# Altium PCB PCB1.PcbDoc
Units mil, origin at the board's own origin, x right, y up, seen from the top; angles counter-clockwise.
Board outline 2756 x 2756 mil, 4 copper layers (Top Layer, Internal Plane 1, Internal Plane 2, Bottom Layer), stack 18.2 mil thick; 13 components, 14 nets, 56 pads, 0 vias.
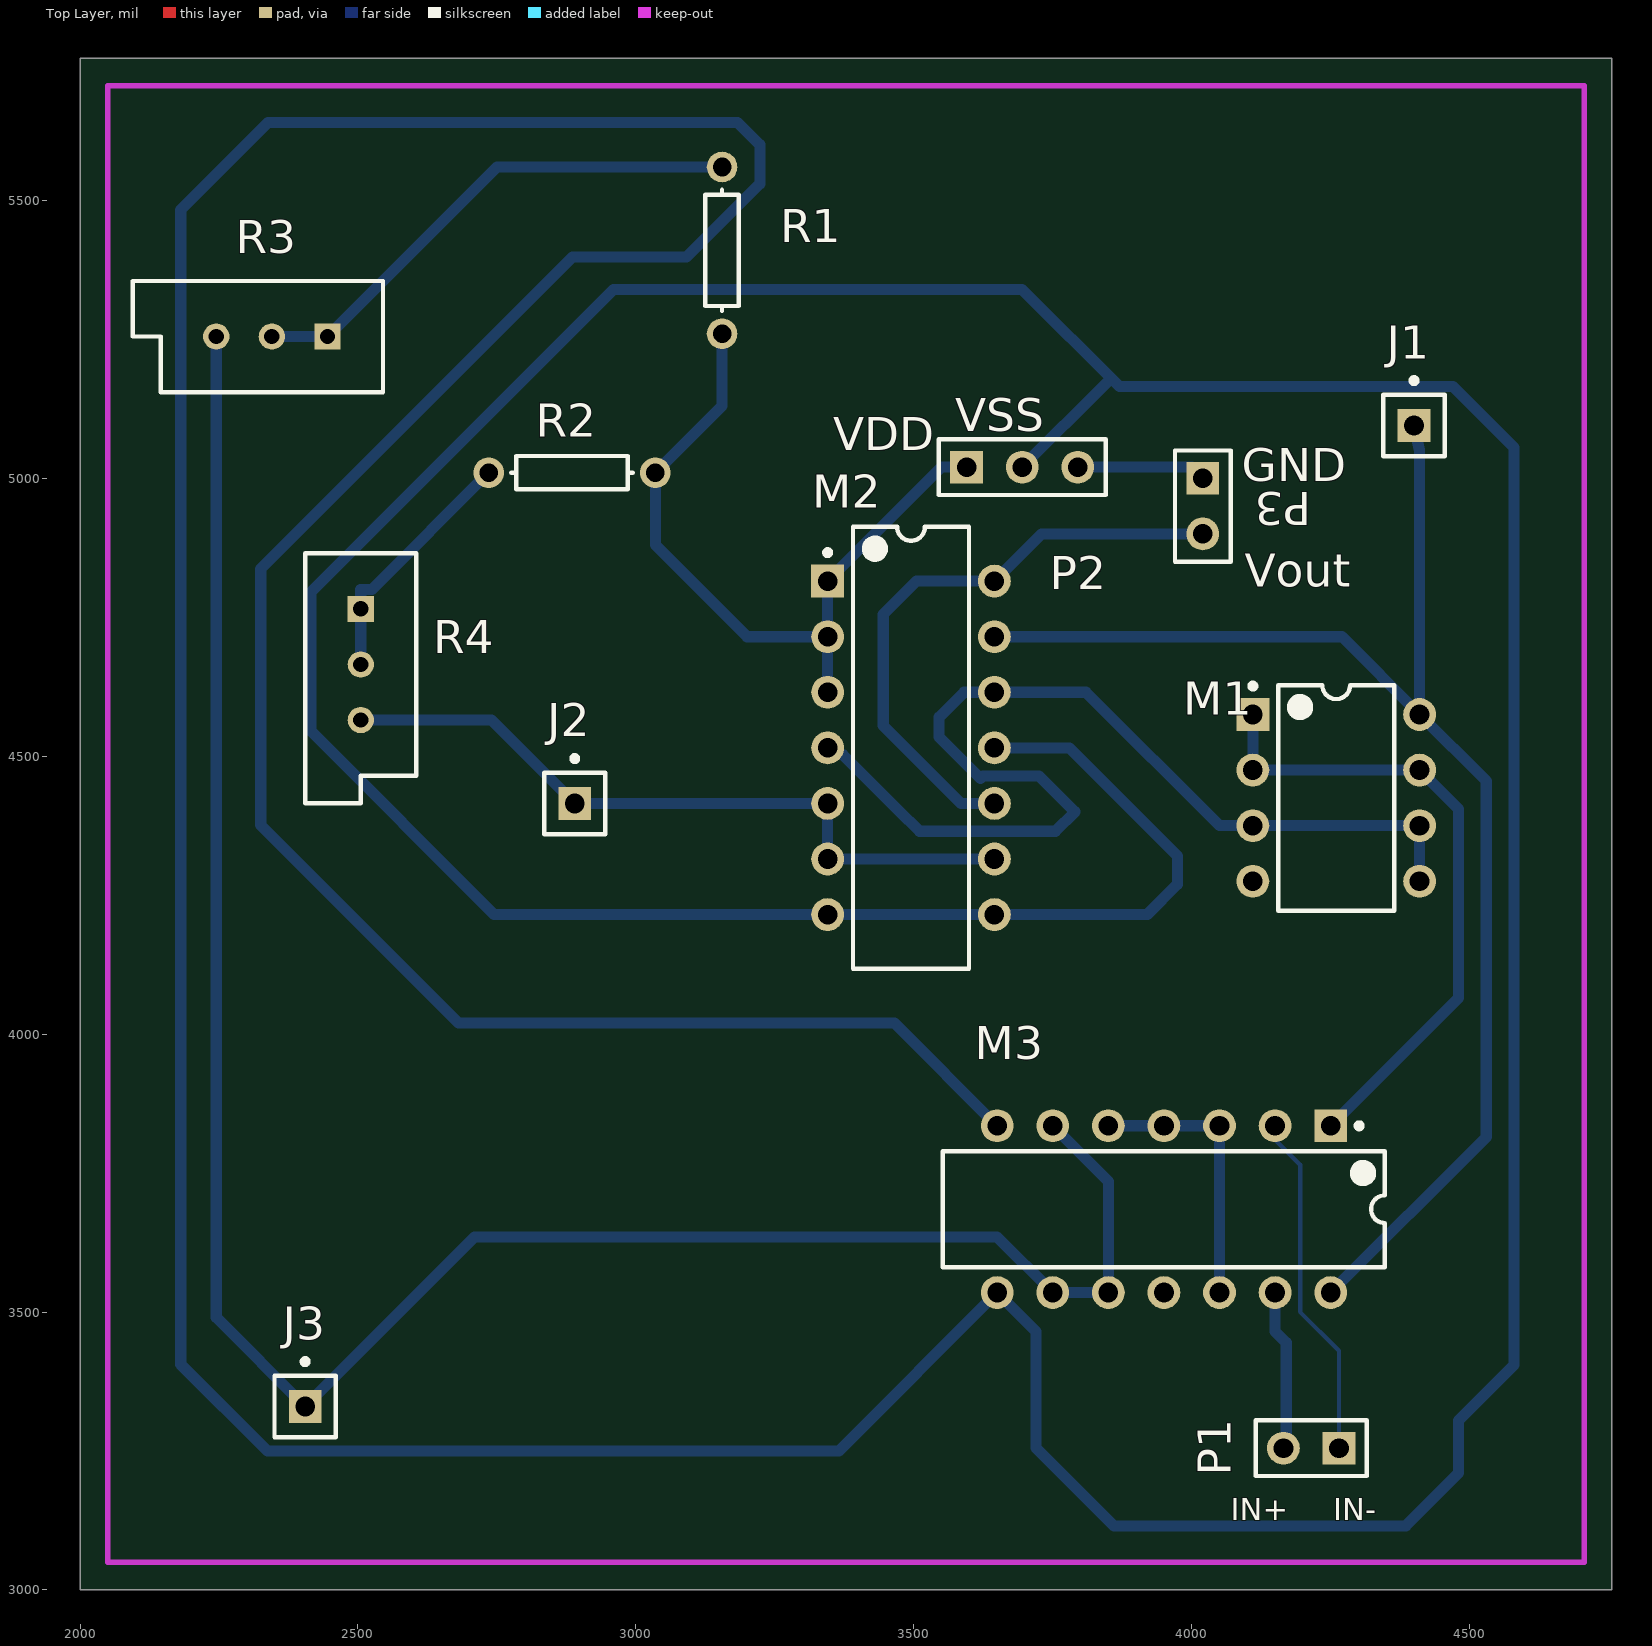
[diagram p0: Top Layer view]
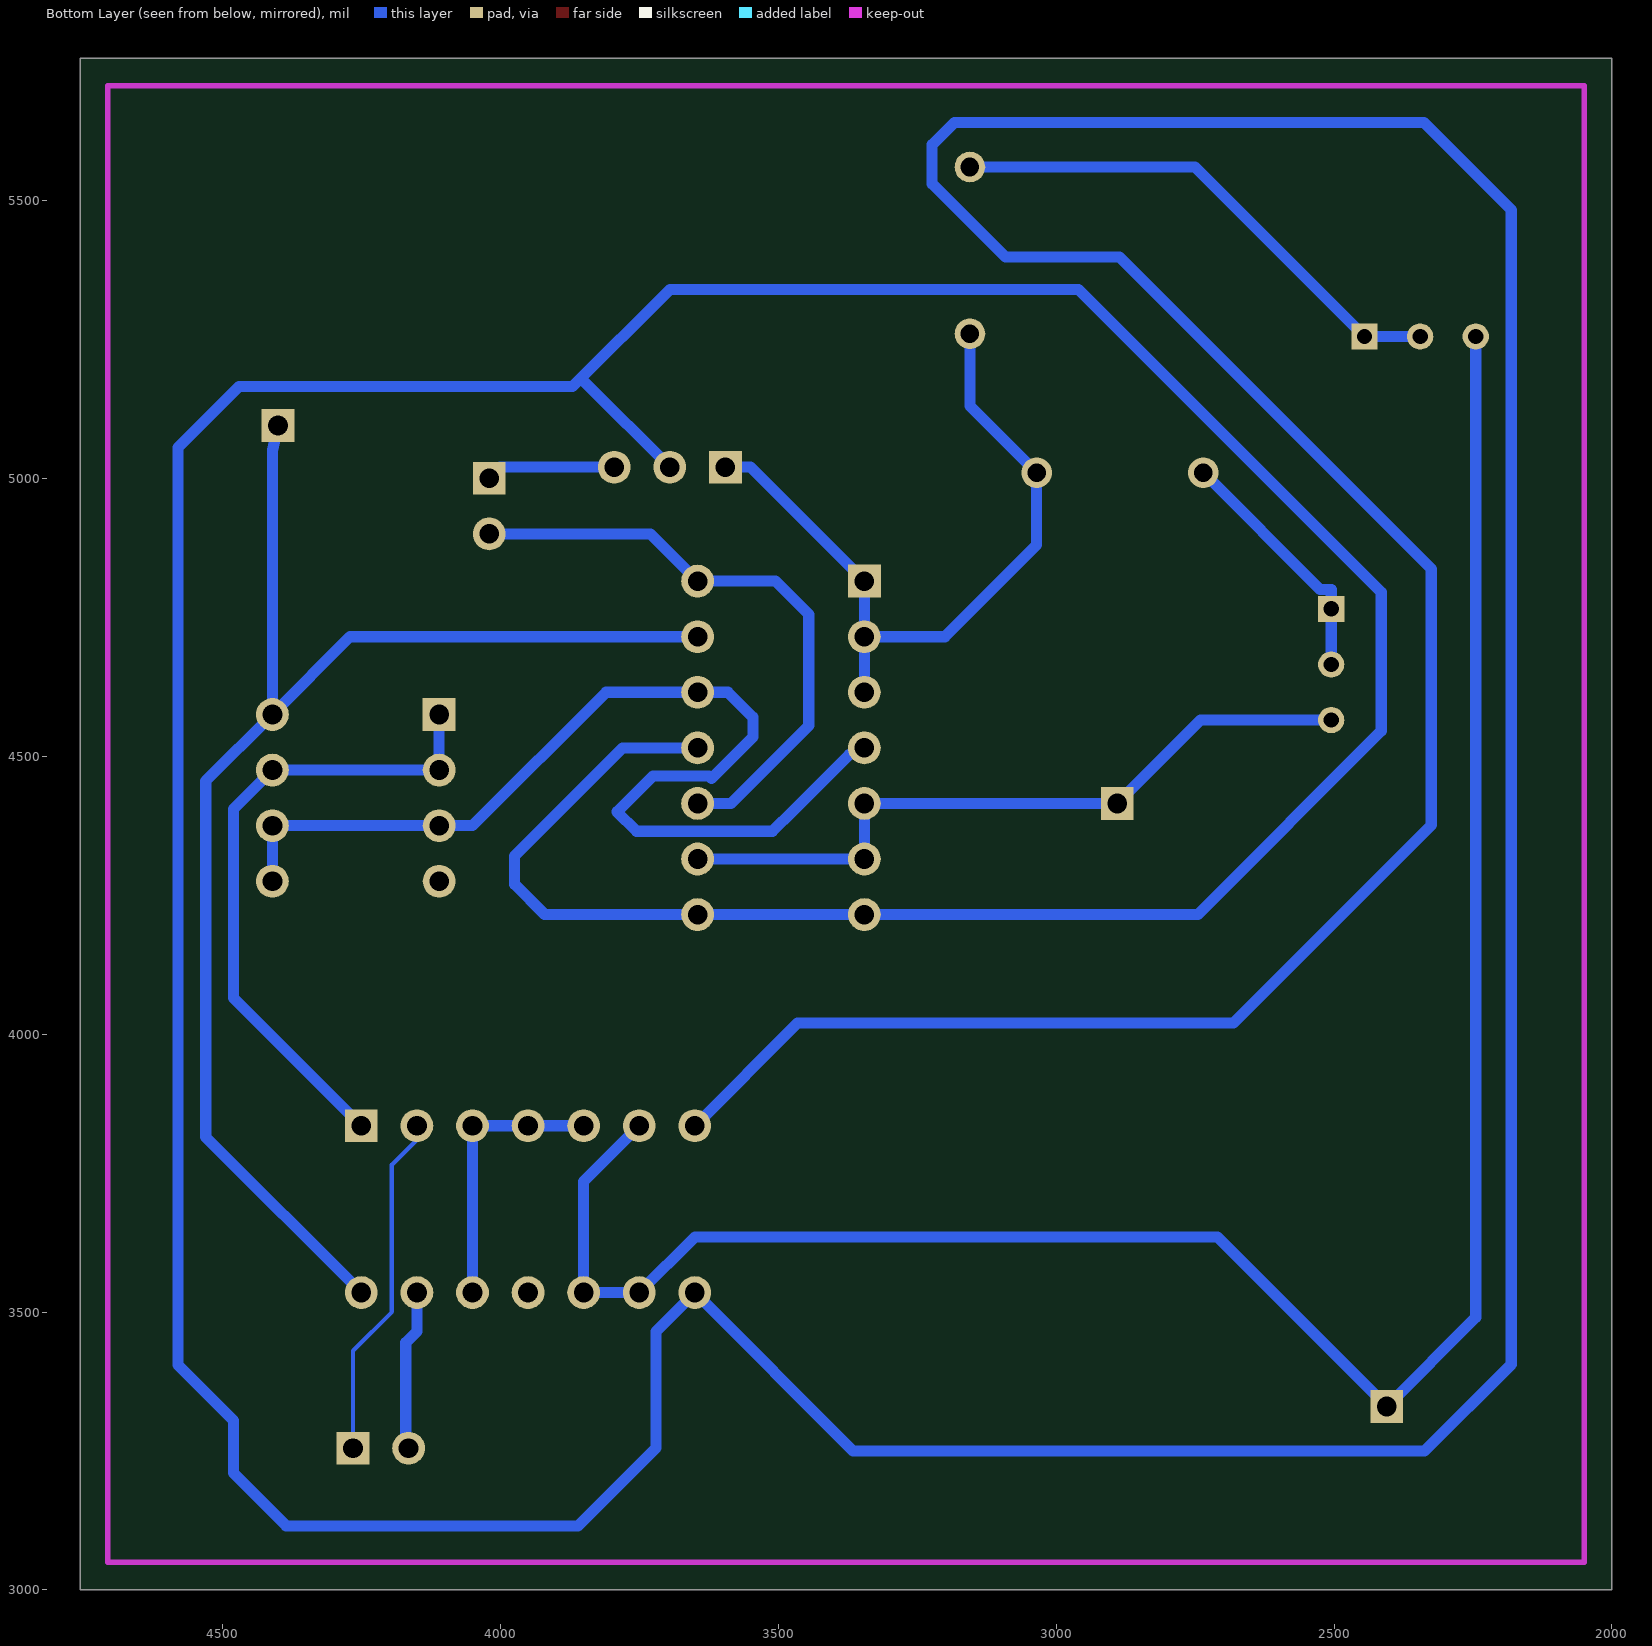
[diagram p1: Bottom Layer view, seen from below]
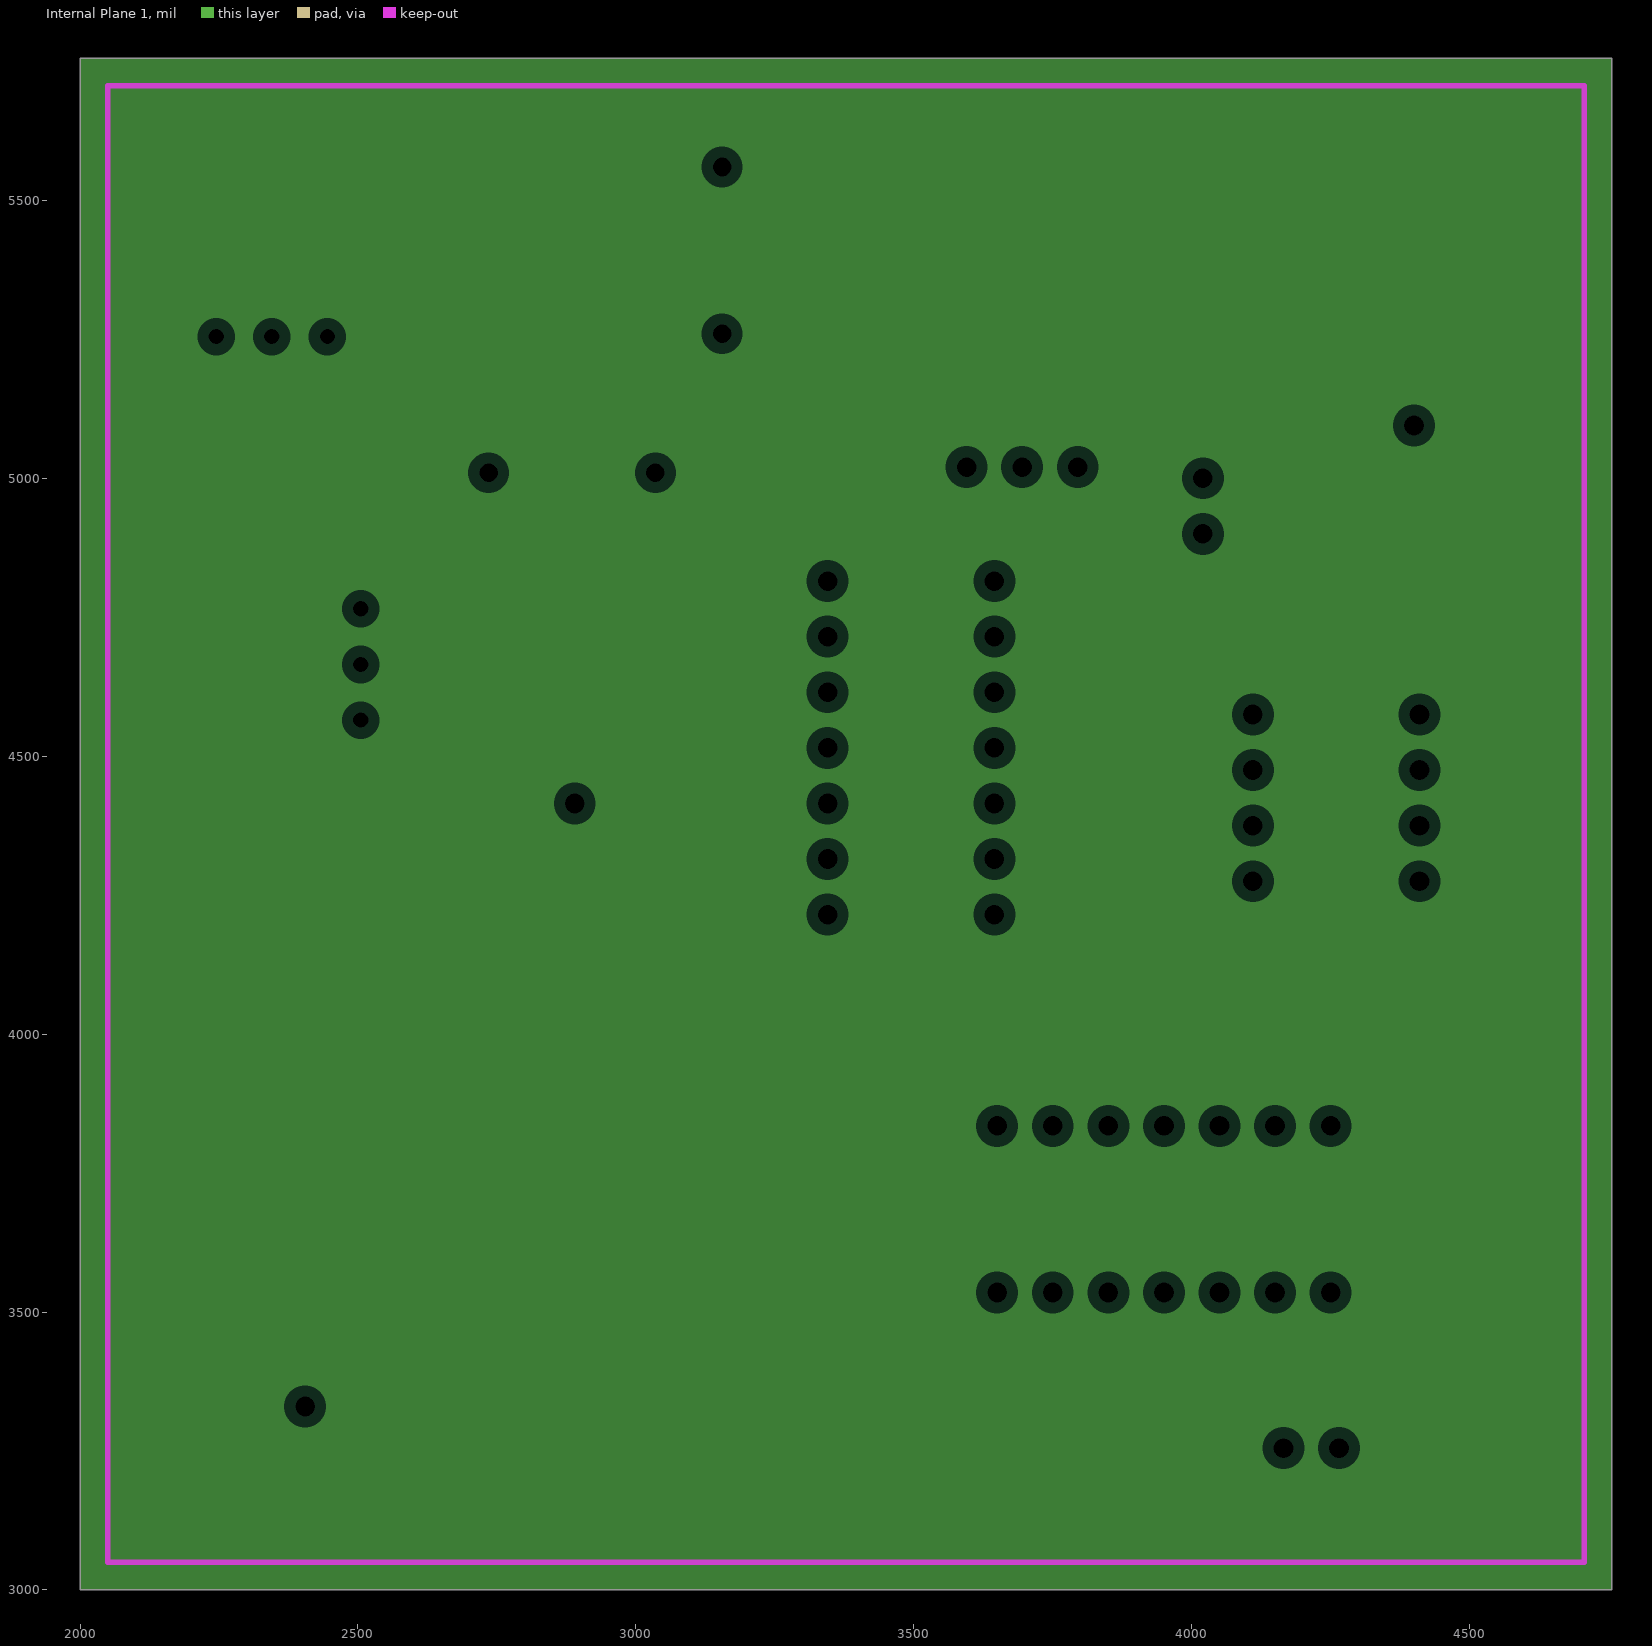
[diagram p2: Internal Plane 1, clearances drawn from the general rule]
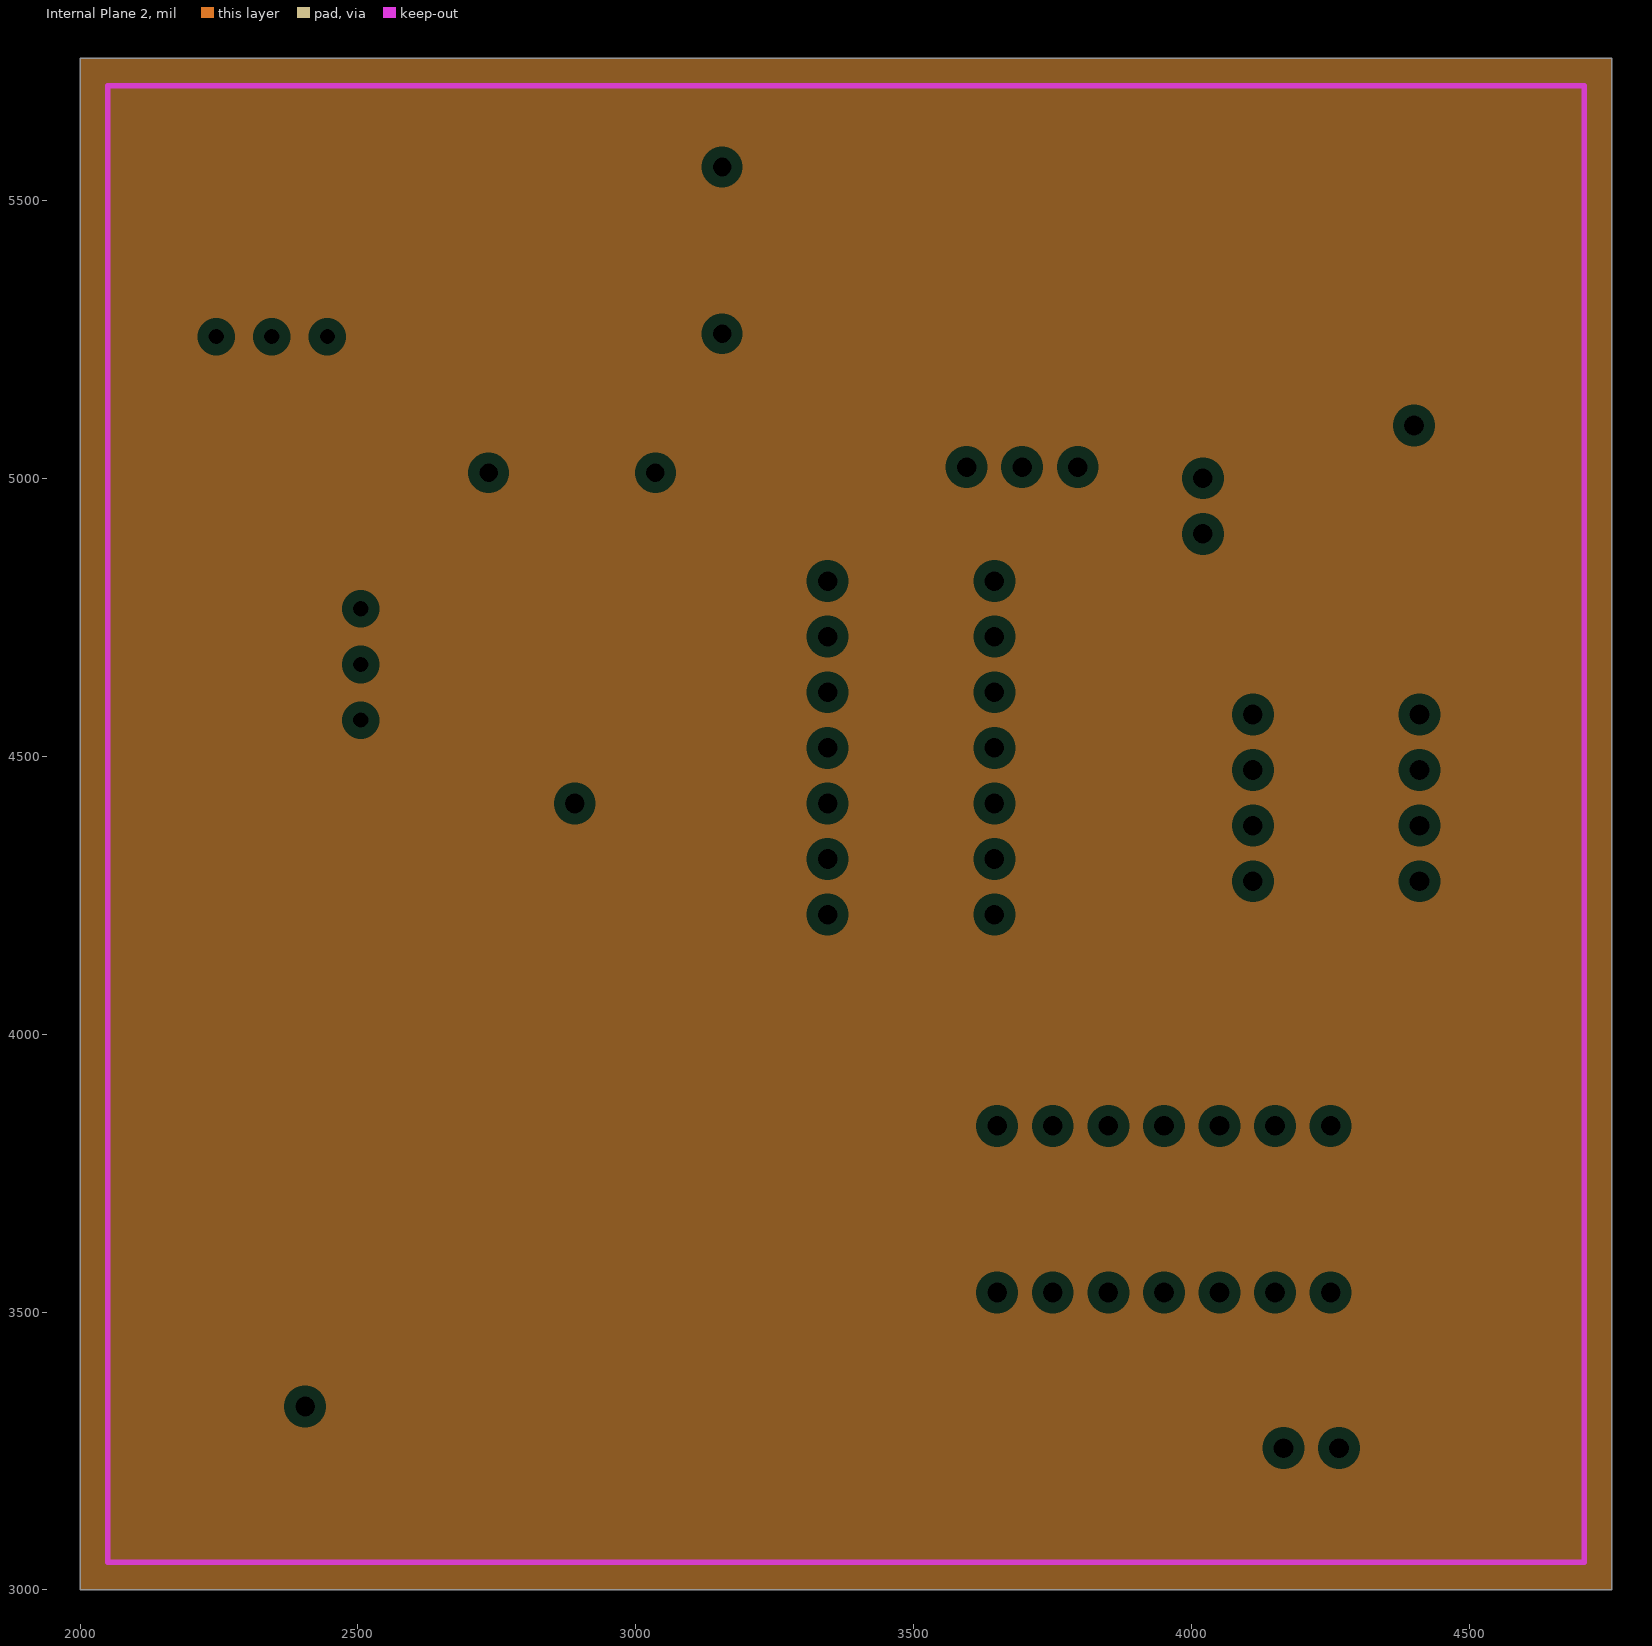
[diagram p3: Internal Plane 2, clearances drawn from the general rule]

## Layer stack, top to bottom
Top Solder: solder mask 0.4, Solder Resist, Dk 3.5
Top Layer: signal copper 1.4
Internal Plane 1: plane copper 1.4
Internal Plane 2: plane copper 1.4
Dielectric 1: dielectric 12.6, FR-4, Dk 4.8
Bottom Layer: signal copper 1.4
Bottom Solder: solder mask 0.4, Solder Resist, Dk 3.5

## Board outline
2000,3000 4756,3000 4756,5756 2000,5756

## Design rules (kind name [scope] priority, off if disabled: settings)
Clearance Clearance_3 [InNet('NetM1_3')] p1: gap=10
Clearance Clearance_2 [InNet('NetJ1_1')] p2: gap=10
Clearance Clearance_1 [InNet('IN+')] p3: gap=0
Clearance [All] p4: gap=30
PlaneClearance [All] p1: clearance=20
PlaneConnect [All] p1: planeconnectstyle=Relief reliefexpansion=20 reliefentries=4 reliefconductorwidth=10 reliefairgap=10
PolygonConnect [All] p1: connectstyle=Relief reliefconductorwidth=10 reliefentries=4 polygonreliefangle="90 Angle" airgapwidth=10
RoutingVias [All] p1: holewidth=32 width=62 viastyle="Through Hole" minholewidth=28 minwidth=50 maxholewidth=28 maxwidth=50
SolderMaskExpansion [All] p1: expansion=4
Width [All] p1: maxlimit=20 minlimit=8 preferedwidth=20 toplayer_minwidth=20 minimp=50.000000 maximp=50.000000 favimp=50.000000
28 further rules are at their usual default settings.

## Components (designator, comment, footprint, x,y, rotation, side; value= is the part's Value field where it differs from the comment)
J1 "Socket" PIN1 4400,5095 r0 top
J2 "Socket" PIN1 2890,4415 r0 top
J3 "Socket" PIN1 2405,3330 r0 top
M1 "ALD1117" DIP-8 4260,4425 r0 top
M2 "ALD1105" DIP-14 3495,4515 r0 top
M3 "ALD1106" DIP-14 3950,3685 r270 top
P1 "Header 2" HDR1X2 4265,3255 r180 top
P2 "Header 3" HDR1X3 3595,5020 r0 top
P3 "Header 2" HDR1X2 4020,5000 r270 top
R1 "Res1" AXIAL-0.3 3155,5410 r270 top
R2 "Res1" AXIAL-0.3 2885,5010 r0 top
R3 "RPot" VR5 2345,5255 r180 top
R4 "RPot" VR5 2505,4665 r270 top

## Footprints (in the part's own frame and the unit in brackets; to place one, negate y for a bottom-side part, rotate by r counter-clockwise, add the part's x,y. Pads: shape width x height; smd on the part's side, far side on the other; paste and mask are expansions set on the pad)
AXIAL-0.3 [mm] "Axial Device, Thru-Hole; 2 Leads; 0.3 in Pin Spacing"
  round 1.4 hole 0.85: 1(-3.81,0) 2(3.81,0)
  silkscreen extent -2.77,-0.76 2.77,0.76
DIP-8 [mm] "DIP, 8-Pin, Row Spacing 7.62 mm, Pitch 2.54 mm"
  rect 1.5x1.5 hole 0.9: 1(-3.81,3.81)
  round 1.5 hole 0.9: 2(-3.81,1.27) 3(-3.81,-1.27) 4(-3.81,-3.81) 5(3.81,-3.81) 6(3.81,-1.27) 7(3.81,1.27) 8(3.81,3.81)
  silkscreen extent -3.93,-5.15 2.65,5.23, body extent -3.6,-5.15 3.6,5.15, height 5.33
DIP-14 [mm] "DIP, 14-Pin, Row Spacing 7.62 mm, Pitch 2.54 mm"
  rect 1.5x1.5 hole 0.9: 1(-3.81,7.62)
  round 1.5 hole 0.9: 2(-3.81,5.08) 3(-3.81,2.54) 4(-3.81,0) 5(-3.81,-2.54) 6(-3.81,-5.08) 7(-3.81,-7.62) 8(3.81,-7.62) 9(3.81,-5.08) 10(3.81,-2.54) 11(3.81,0) 12(3.81,2.54) 13(3.81,5.08) 14(3.81,7.62)
  silkscreen extent -3.93,-10.1 2.65,10.1, body extent -3.6,-10.1 3.6,10.1, height 5.08
HDR1X2 [mm] "Connector; Header; 2 Position"
  rect 1.5x1.5 hole 0.9: 1(0,0)
  round 1.5 hole 0.9: 2(2.54,0)
  silkscreen extent -1.27,-1.27 3.81,1.27
HDR1X3 [mm] "Connector; Header; 3 Position"
  rect 1.5x1.5 hole 0.9: 1(0,0)
  round 1.5 hole 0.9: 2(2.54,0) 3(5.08,0)
  silkscreen extent -1.27,-1.27 6.35,1.27
PIN1 [mm] "Connector; Plug"
  rect 1.5x1.5 hole 0.9: 1(0,0)
  silkscreen extent -1.4,-1.4 1.4,2.17
VR5 [mm] "Thru-Hole; 3 Leads"
  rect 1.2x1.2 hole 0.7: 1(-2.54,0)
  round 1.2 hole 0.7: 2(0,0) 3(2.54,0)
  silkscreen extent -5.08,-2.54 6.35,2.54

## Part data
M1: "Dual P-channel matched MOSFET array"
M2: "Dual P-channel and dual N-channel matched MOSFET array"
M3: "Quad N-channel matched MOSFET array"
P1 P3: "Header, 2-Pin"
P2: "Header, 3-Pin"
R1 R2: "Resistor"
R3 R4: "Potentiometer"

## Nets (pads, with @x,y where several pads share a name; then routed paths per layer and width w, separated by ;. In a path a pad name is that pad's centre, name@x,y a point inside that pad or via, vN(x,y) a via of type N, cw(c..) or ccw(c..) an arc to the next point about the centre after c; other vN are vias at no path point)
GND: P2.3 P3.1 | length 205
  Bottom Layer w20: P2.3 P3.1@4000,5020
IN+: M3.13 P1.2 | length 278.3
  Bottom Layer w20: M3.13 4150,3465 4170,3445 P1.2@4170,3265
IN-: M3.2 P1.1 | length 627.6
  Bottom Layer w8: M3.2 4150,3810 4195,3765 4195,3500.16 4265,3430.16 P1.1
NetJ1_1: J1.1 M1.8 M2.13 M3.14 | length 2549.8
  Bottom Layer w20: M2.13 4270,4715 M1.8 ; M3.14 4530,3815 4530,4455 M1.8 ; J1.1 4410,5050 M1.8
NetJ2_1: J2.1 M2.5 M2.6 M2.9 R4.3 | length 1302.1
  Bottom Layer w20: R4.3 2740,4565 J2.1 M2.5 M2.6 M2.9
NetJ3_1: J3.1 M3.6 M3.9 M3.10 R3.3 | length 3945.5
  Bottom Layer w20: R3.3 2245,3490 J3.1 2710,3635 3650,3635 M3.9 M3.10 3850,3735 M3.6
NetM1_1: M1.1 M1.2 M1.7 M3.1 | length 1164.3
  Bottom Layer w20: M1.1 M1.2 M1.7 4480,4405 4480,4065 M3.1
NetM1_3: M1.3 M1.5 M1.6 M2.4 M2.12 | length 1911.7
  Bottom Layer w20: 3372.5,4502.5 3472.5,4402.5 3510,4365 3755,4365 3790,4400 3725.47,4464.53 3624.49,4464.53 3619.96,4460 3545,4534.96 3545,4570 3590,4615 M2.12 3810,4615 4050,4375 M1.3 M1.6 M1.5
NetM3_3: M3.3 M3.4 M3.5 M3.12 | length 500
  Bottom Layer w20: M3.5 M3.4 M3.3 M3.12
NetR1_1: R1.1 R3.1 R3.2 | length 936.3
  Bottom Layer w20: R3.2 R3.1 2750,5560 R1.1
NetR2_1: R2.1 R4.1 R4.2 | length 452
  Bottom Layer w20: R4.2 R4.1 2505,4800 2525,4800 R2.1
VDD: M2.1 M2.2 M2.3 P2.1 R1.2 R2.2 | length 1343
  Bottom Layer w20: R1.2 3155,5130 R2.2 3035,4880 3200,4715 M2.2 ; M2.3 M2.2 ; P2.1 3550,5020 M2.1 M2.2
VO2: M2.10 M2.14 P3.2 | length 1093.1
  Bottom Layer w20: M2.10 3585,4415 3445,4555 3445,4755 3505,4815 M2.14 3730,4900 P3.2
VSS: M2.7 M2.8 M2.11 M3.7 M3.8 P2.2 | length 16331.6
  Top Layer w20: P2.2 P2.2@3700,5025
  Bottom Layer w20: M2.11 3780,4515 3974.64,4320.36 3974.64,4269.64 3920,4215 M2.8 M2.7 2745,4215 2415,4545 2415,4795 2960,5340 3695,5340 3870,5165 4470,5165 4580,5055 4580,3405 4480,3305 4480,3210 4385,3115 3860,3115 3720,3255 3720,3465 M3.8 3365,3250 2337,3250 2181,3406 2181,5483 2337.96,5639.96 3183.04,5639.96 3223,5600 3223,5530 3091,5398 2886,5398 2325,4837 2325,4376 2681,4020 3465,4020 M3.7 ; P2.2 3847.5,5172.5
pads on no net: M1.4 M3.11

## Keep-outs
Keep-Out Layer:
  lines w10: 2050,3050 2050,5706 4706,5706 4706,3050 2050,3050

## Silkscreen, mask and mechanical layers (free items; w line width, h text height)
Top Overlay:
  text "VSS" at 3575,5085 h60
  text "VDD" at 3355,5050 h60
  text "GND" at 4090,4995 h60
  text "Vout" at 4095,4805.01 h60
  text "IN+" at 4070,3125 h40
  text "IN-" at 4255,3125 h40
Drill Drawing:
  text ".LEGEND" at 4956,3200 h60
  text "Drill Drawing." at 4956,3100 h60

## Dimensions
2050,3050 to 2050,5706 on Mechanical 1
2050,3050 to 4706,3050 on Mechanical 1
